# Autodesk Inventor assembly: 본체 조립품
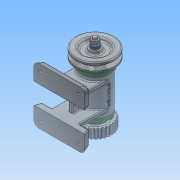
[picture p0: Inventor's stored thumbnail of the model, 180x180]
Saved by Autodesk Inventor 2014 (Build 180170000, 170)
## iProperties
Created: 2016-07
Part Number: 본체 조립품
Document SubType Name: Assembly
Designer: NET
Author: NET
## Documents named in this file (14)
- C:\Users\NET\Desktop\460707V1023\본체 조립품.iam
- C:\Users\NET\Desktop\460707V1023\본체 1pt.ipt
- C:\Users\NET\Desktop\460707V1023\커버.ipt
- C:\Users\NET\Desktop\460707V1023\축.ipt
- C:\Users\NET\Desktop\460707V1023\베어링 15 x 32 x 9.ipt
- C:\Users\NET\Desktop\460707V1023\오일 실 15 25 7.ipt
- C:\Users\NET\Desktop\460707V1023\키 3 x 3 x 12.ipt
- C:\Users\NET\Desktop\460707V1023\볼트 M4 x 12.ipt
- C:\Users\NET\Desktop\460707V1023\니플 M 6 x 0.75.ipt
- C:\Users\NET\Desktop\460707V1023\V벨트풀리.ipt
- C:\Users\NET\Desktop\460707V1023\스퍼기어.ipt
- C:\Users\NET\Desktop\460707V1023\와셔 8x17.ipt
- C:\Users\NET\Desktop\460707V1023\스프링와셔 8.ipt
- C:\Users\NET\Desktop\460707V1023\너트 M 8.ipt
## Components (11 placed, 3 different names)
1. KS B 2023 6002 - 15 x 32 x 9:1
2. KS B 2023 6002 - 15 x 32 x 9:2
3. V벨트풀리:1
4. ISO 4762 M4 x 12:1
5. ISO 4762 M4 x 12:3
6. ISO 4762 M4 x 12:4
7. ISO 4762 M4 x 12:5
8. ISO 4762 M4 x 12:2
9. ISO 4762 M4 x 12:6
10. ISO 4762 M4 x 12:7
11. ISO 4762 M4 x 12:8
